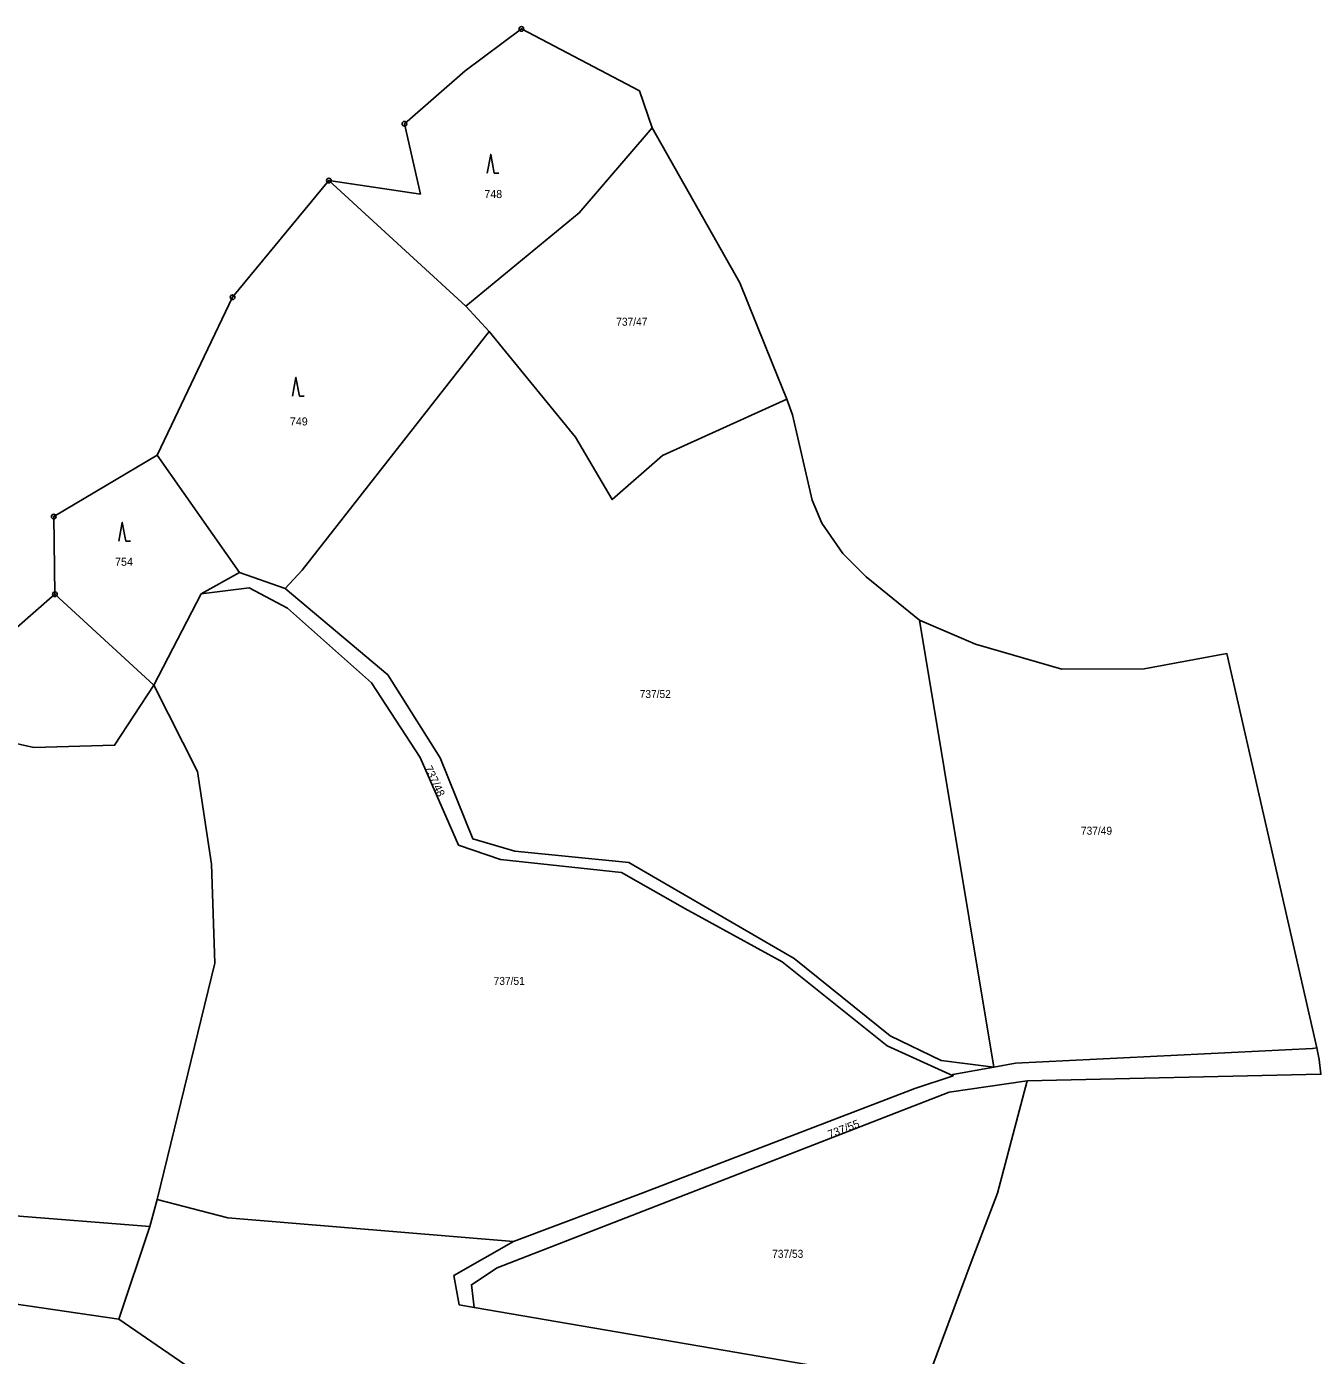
# Model space of a CAD drawing. Extents: x -687135 to -684370, y -1007309 to -1005782.
# Drawn here: x -686882.4 to -686608.2, y -1006425.4 to -1006143.1 of the extents above; entities that cross this region are included whole.
import ezdxf

# ---------------------------------------------------------------- set-up
doc = ezdxf.new("R2010")
doc.units = 0
doc.header["$LTSCALE"] = 0.68
for name, color, linetype, lineweight in [('1', 7, 'Continuous', 25), ('3', 7, 'Continuous', 25), ('8', 7, 'Continuous', 25)]:
    doc.layers.add(name, color=color, linetype=linetype, lineweight=lineweight)
doc.layers.add('2', color=7, linetype='Continuous')

msp = doc.modelspace()

# ---------------------------------------------------------------- linework, layer by layer
at = {"layer": '1'}
for p, q in [((-686777.28, -1006143.65), (-686752.2, -1006156.77)), ((-686818.17, -1006175.86), (-686838.61, -1006200.64)), ((-686818.17, -1006175.86), (-686789.09, -1006202.56)), ((-686784.14, -1006207.92), (-686789.09, -1006202.56)), ((-686854.64, -1006234.16), (-686876.6, -1006247.24)), ((-686876.6, -1006247.24), (-686876.35, -1006263.75)), ((-686845.28, -1006263.67), (-686837.18, -1006259.14)), ((-686876.35, -1006263.75), (-686888.56, -1006274.33))]:
    msp.add_line(p, q, dxfattribs=at)
for points in [[(-686777.28, -1006143.65), (-686789.2, -1006152.52), (-686802.13, -1006163.8), (-686798.72, -1006178.72), (-686818.17, -1006175.86)], [(-686789.09, -1006202.56), (-686765, -1006182.74), (-686749.53, -1006164.64), (-686752.2, -1006156.77)], [(-686720.94, -1006222.27), (-686723.97, -1006214.79), (-686730.93, -1006197.61), (-686749.53, -1006164.64)], [(-686838.61, -1006200.64), (-686844.65, -1006213.26), (-686851.6, -1006227.8), (-686854.64, -1006234.16)], [(-686827.48, -1006262.51), (-686823.86, -1006258.64), (-686784.14, -1006207.92)], [(-686784.14, -1006207.92), (-686765.81, -1006230.39), (-686758, -1006243.63), (-686747.32, -1006234.27), (-686720.94, -1006222.27)], [(-686692.71, -1006269.21), (-686704.09, -1006260.04), (-686709.05, -1006255.1), (-686713.5, -1006248.65), (-686715.57, -1006243.75), (-686719.74, -1006225.59), (-686720.94, -1006222.27)], [(-686854.64, -1006234.16), (-686837.18, -1006259.14), (-686827.48, -1006262.51)], [(-686845.28, -1006263.67), (-686835.1, -1006262.39), (-686826.99, -1006266.72), (-686809.11, -1006282.55), (-686798.76, -1006298.43), (-686790.64, -1006317.02), (-686781.71, -1006320.07), (-686756, -1006322.88), (-686742.6, -1006330.47), (-686721.92, -1006341.8), (-686699.62, -1006359.65), (-686685.56, -1006366.06)], [(-686676.96, -1006364.22), (-686688.11, -1006362.75), (-686698.99, -1006357.53), (-686719.33, -1006341.08), (-686754.48, -1006320.74), (-686778.66, -1006318.33), (-686787.59, -1006315.72), (-686794.56, -1006298.51), (-686805.66, -1006280.87), (-686827.48, -1006262.51)], [(-686876.35, -1006263.75), (-686855.34, -1006283.06), (-686845.28, -1006263.67)], [(-686686.76, -1006271.77), (-686692.71, -1006269.21), (-686676.96, -1006364.22)], [(-686686.76, -1006271.77), (-686680.87, -1006274.31), (-686662.49, -1006279.64), (-686645.03, -1006279.61), (-686627.47, -1006276.35), (-686608.39, -1006360.12), (-686607.84, -1006362.54)], [(-686856.22, -1006398.01), (-686886.59, -1006395.67), (-686923.95, -1006392.28), (-686995.5, -1006379.79), (-687033.91, -1006376.19), (-687045.92, -1006364.66), (-687051.68, -1006362.98), (-687047.45, -1006337.49), (-687034.02, -1006314.1), (-687030.55, -1006301.13), (-687017.58, -1006302.52), (-686999.06, -1006300.2), (-686986.32, -1006300.2), (-686969.19, -1006296.5), (-686946.27, -1006300.9), (-686901.65, -1006291.63), (-686880.81, -1006296.26), (-686863.68, -1006295.8), (-686855.34, -1006283.06)], [(-686854.61, -1006392.29), (-686842.37, -1006342.13), (-686843.07, -1006321.05), (-686846.08, -1006301.36), (-686855.34, -1006283.06)], [(-686676.96, -1006364.22), (-686672.32, -1006363.32), (-686609.25, -1006360.2), (-686608.39, -1006360.12)], [(-686685.56, -1006366.06), (-686685.67, -1006365.73), (-686676.96, -1006364.22)], [(-686669.85, -1006367.08), (-686607.48, -1006365.69), (-686607.84, -1006362.54)], [(-686669.85, -1006367.08), (-686686.46, -1006369.51), (-686782.46, -1006406.79), (-686787.9, -1006410.41), (-686787.33, -1006415.27)], [(-686778.97, -1006401.2), (-686751.85, -1006391), (-686693.76, -1006368.71), (-686685.56, -1006366.06)], [(-686691.44, -1006431.67), (-686681.78, -1006405.61), (-686676.16, -1006390.95), (-686669.85, -1006367.08)], [(-686778.97, -1006401.2), (-686839.63, -1006396.21), (-686854.61, -1006392.29), (-686856.22, -1006398.01), (-686862.81, -1006417.73)], [(-686862.81, -1006417.73), (-686982.17, -1006400.27), (-686984.16, -1006422.05)], [(-686787.33, -1006415.27), (-686790.47, -1006414.7), (-686791.6, -1006408.48), (-686778.97, -1006401.2)], [(-686694.78, -1006441.51), (-686691.95, -1006433.27), (-686691.44, -1006431.67), (-686787.33, -1006415.27)], [(-686705.53, -1006469.79), (-686751.17, -1006462.19), (-686795.04, -1006458.78), (-686830.03, -1006440.24), (-686862.81, -1006417.73)]]:
    msp.add_lwpolyline(points, dxfattribs=at)
at = {"layer": '3'}
for p, q in [((-686783.05, -1006174.29), (-686782.054, -1006174.29)), ((-686824.41, -1006221.69), (-686823.414, -1006221.69)), ((-686861.3, -1006252.47), (-686860.304, -1006252.47))]:
    msp.add_line(p, q, dxfattribs=at)
for points in [[(-686783.05, -1006174.29), (-686783.8, -1006170.29), (-686784.55, -1006174.29)], [(-686824.41, -1006221.69), (-686825.16, -1006217.69), (-686825.91, -1006221.69)], [(-686861.3, -1006252.47), (-686862.05, -1006248.47), (-686862.8, -1006252.47)]]:
    msp.add_lwpolyline(points, dxfattribs=at)
at = {"layer": '8'}
for centre, radius in [((-686777.28, -1006143.6499), 0.5), ((-686777.28, -1006143.6499), 0.0303), ((-686802.13, -1006163.7999), 0.5), ((-686802.13, -1006163.7999), 0.0303), ((-686818.17, -1006175.8599), 0.5), ((-686818.17, -1006175.8599), 0.0303), ((-686838.61, -1006200.6399), 0.5), ((-686838.61, -1006200.6399), 0.0303), ((-686876.6, -1006247.2399), 0.5), ((-686876.6, -1006247.2399), 0.0303), ((-686876.35, -1006263.7499), 0.5), ((-686876.35, -1006263.7499), 0.0303)]:
    msp.add_circle(centre, radius, dxfattribs=at)

# ---------------------------------------------------------------- texts
at = {"layer": '2'}
for s, p in [('748', (-686785.16, -1006179.58)), ('749', (-686826.45, -1006227.88)), ('754', (-686863.58, -1006257.69))]:
    msp.add_text(s, height=1.7, dxfattribs=at).set_placement(p)
at = {"layer": '2', "width": 0.95}
for s, p in [('737/47', (-686757.14, -1006206.7)), ('737/52', (-686752.16, -1006285.78)), ('737/49', (-686658.45, -1006314.82)), ('737/51', (-686783.18, -1006346.73)), ('737/53', (-686724.03, -1006404.7))]:
    msp.add_text(s, height=1.7, dxfattribs=at).set_placement(p)
at = {"layer": '2'}
for s, rotation, p in [('737/48', 295, (-686797.92, -1006300.619)), ('737/55', 21, (-686711.805, -1006379.343))]:
    msp.add_text(s, height=1.7, rotation=rotation, dxfattribs=at).set_placement(p)

doc.saveas('drawing.dxf')
